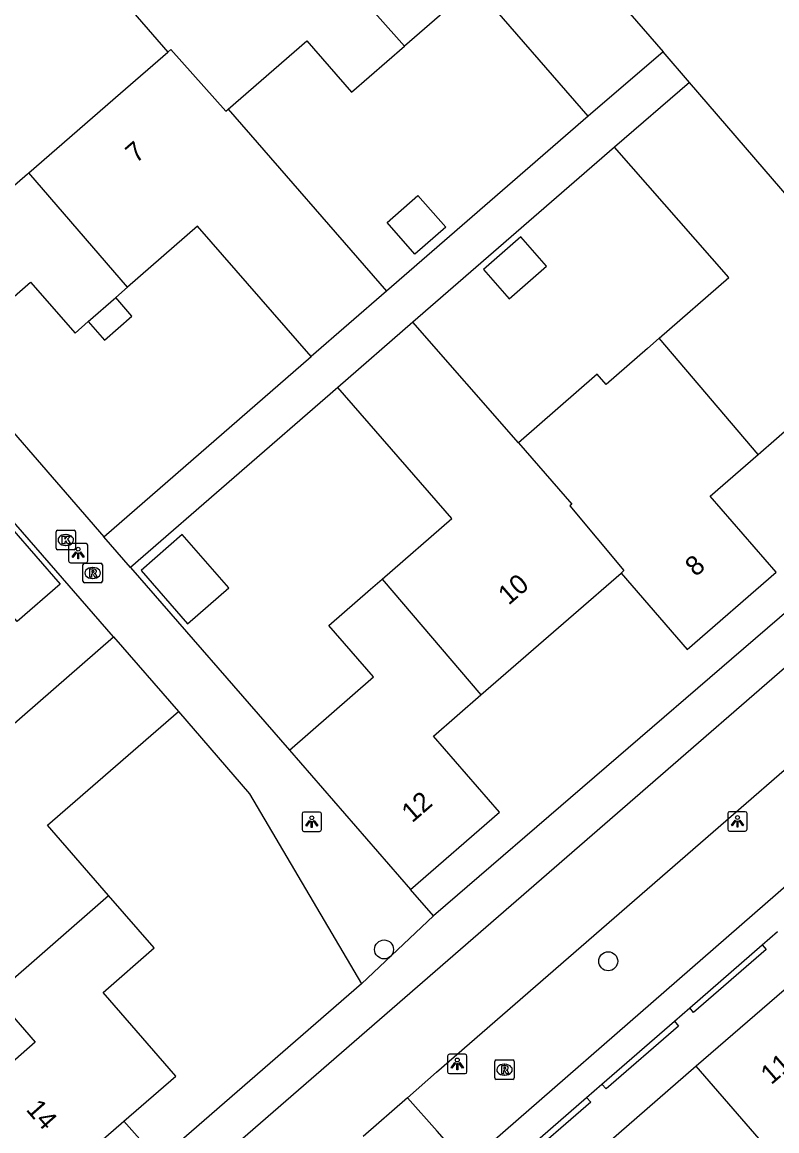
# Model space of a CAD drawing. Extents: x 155888 to 156864, y 383882 to 384671.
# Drawn here: x 156692.5 to 156731.4, y 384304.1 to 384361.3 of the extents above; entities that cross this region are included whole.
import ezdxf

# ---------------------------------------------------------------- set-up
doc = ezdxf.new("R2010")
doc.units = 0
for name, color, linetype in [('IMGEO_Boom', 7, 'Continuous'), ('IMGEO_Kolk', 7, 'Continuous'), ('IMGEO_Lichtpunt', 7, 'Continuous'), ('IMGEO_Muur', 7, 'Continuous'), ('IMGEO_Pand', 7, 'Continuous'), ('IMGEO_Pand_nummerreeks', 7, 'Continuous'), ('IMGEO_Rijbaan_lokaal_gesloten', 7, 'Continuous'), ('IMGEO_Rioolput', 7, 'Continuous'), ('IMGEO_Voetpad_open', 7, 'Continuous')]:
    doc.layers.add(name, color=color, linetype=linetype)

msp = doc.modelspace()

# ---------------------------------------------------------------- linework, layer by layer
at = {"layer": 'IMGEO_Boom'}
for centre in [(156711.122, 384313.445), (156722.688, 384312.836)]:
    msp.add_circle(centre, 0.489, dxfattribs=at)
at = {"layer": 'IMGEO_Kolk'}
for p, q in [((156694.205, 384334.142), (156694.205, 384334.994)), ((156694.28, 384335.068), (156695.132, 384335.068)), ((156694.693, 384334.848), (156694.718, 384334.848)), ((156695.206, 384334.994), (156695.206, 384334.142)), ((156694.716, 384334.288), (156694.691, 384334.288)), ((156695.132, 384334.068), (156694.28, 384334.068))]:
    msp.add_line(p, q, dxfattribs=at)
for points in [[(156694.205, 384334.142), (156694.205, 384334.994)], [(156694.28, 384335.068), (156695.132, 384335.068)], [(156695.206, 384334.994), (156695.206, 384334.142)], [(156694.526, 384334.768), (156694.649, 384334.768), (156694.649, 384334.617), (156694.779, 384334.768), (156694.943, 384334.768), (156694.797, 384334.617), (156694.95, 384334.368), (156694.798, 384334.368), (156694.713, 384334.532), (156694.649, 384334.465), (156694.649, 384334.368), (156694.526, 384334.368), (156694.526, 384334.768)], [(156695.132, 384334.068), (156694.28, 384334.068)]]:
    msp.add_lwpolyline(points, dxfattribs=at)
for centre, start, end in [((156694.282, 384334.992), 91.552, 178.448), ((156694.282, 384334.992), 91.552, 178.448), ((156695.13, 384334.992), 1.552, 88.448), ((156695.13, 384334.992), 1.552, 88.448), ((156694.282, 384334.144), 181.552, 268.448), ((156694.282, 384334.144), 181.552, 268.448), ((156695.13, 384334.144), 271.552, 358.448), ((156695.13, 384334.144), 271.552, 358.448)]:
    msp.add_arc(centre, 0.0765, start, end, dxfattribs=at)
for centre, major_axis, ratio, start_param, end_param in [((156694.692, 384334.568), (-0.387, 0.002), 0.722429, 4.712389, 7.853982), ((156694.717, 384334.568), (-0.39, 0.002), 0.717154, 1.570796, 4.712389)]:
    msp.add_ellipse(centre, major_axis=major_axis, ratio=ratio, start_param=start_param, end_param=end_param, dxfattribs=at)
at = {"layer": 'IMGEO_Lichtpunt'}
for p, q in [((156694.846, 384334.295), (156694.846, 384333.488)), ((156694.846, 384334.295), (156694.846, 384333.488)), ((156695.748, 384334.39), (156694.94, 384334.39)), ((156695.748, 384334.39), (156694.94, 384334.39)), ((156695.842, 384333.488), (156695.842, 384334.295)), ((156695.842, 384333.488), (156695.842, 384334.295)), ((156694.94, 384333.394), (156695.748, 384333.394)), ((156694.94, 384333.394), (156695.748, 384333.394)), ((156707.797, 384320.533), (156706.989, 384320.533)), ((156707.797, 384320.533), (156706.989, 384320.533)), ((156729.756, 384320.551), (156728.948, 384320.551)), ((156729.756, 384320.551), (156728.948, 384320.551)), ((156706.895, 384320.438), (156706.895, 384319.631)), ((156706.895, 384320.438), (156706.895, 384319.631)), ((156707.891, 384319.631), (156707.891, 384320.438)), ((156707.891, 384319.631), (156707.891, 384320.438)), ((156728.854, 384320.456), (156728.854, 384319.649)), ((156728.854, 384320.456), (156728.854, 384319.649)), ((156729.85, 384319.649), (156729.85, 384320.456)), ((156729.85, 384319.649), (156729.85, 384320.456)), ((156706.989, 384319.537), (156707.797, 384319.537)), ((156706.989, 384319.537), (156707.797, 384319.537)), ((156728.948, 384319.555), (156729.756, 384319.555)), ((156728.948, 384319.555), (156729.756, 384319.555)), ((156714.402, 384307.945), (156714.402, 384307.138)), ((156714.402, 384307.945), (156714.402, 384307.138)), ((156715.304, 384308.04), (156714.496, 384308.04)), ((156715.304, 384308.04), (156714.496, 384308.04)), ((156715.398, 384307.138), (156715.398, 384307.945)), ((156715.398, 384307.138), (156715.398, 384307.945)), ((156714.496, 384307.044), (156715.304, 384307.044)), ((156714.496, 384307.044), (156715.304, 384307.044))]:
    msp.add_line(p, q, dxfattribs=at)
for points in [[(156695.22, 384333.959), (156695.259, 384333.931), (156695.071, 384333.669), (156695.033, 384333.696), (156695.22, 384333.959)], [(156695.322, 384333.911), (156695.369, 384333.911), (156695.369, 384333.589), (156695.322, 384333.589), (156695.322, 384333.911)], [(156695.432, 384333.931), (156695.47, 384333.958), (156695.657, 384333.696), (156695.618, 384333.668), (156695.432, 384333.931)], [(156707.269, 384320.102), (156707.308, 384320.074), (156707.12, 384319.812), (156707.082, 384319.839), (156707.269, 384320.102)], [(156707.371, 384320.054), (156707.418, 384320.054), (156707.418, 384319.732), (156707.371, 384319.732), (156707.371, 384320.054)], [(156707.481, 384320.074), (156707.519, 384320.101), (156707.706, 384319.839), (156707.667, 384319.811), (156707.481, 384320.074)], [(156729.228, 384320.12), (156729.267, 384320.092), (156729.079, 384319.83), (156729.041, 384319.857), (156729.228, 384320.12)], [(156729.33, 384320.072), (156729.377, 384320.072), (156729.377, 384319.75), (156729.33, 384319.75), (156729.33, 384320.072)], [(156729.44, 384320.092), (156729.478, 384320.119), (156729.665, 384319.857), (156729.626, 384319.829), (156729.44, 384320.092)], [(156714.776, 384307.609), (156714.815, 384307.581), (156714.627, 384307.319), (156714.589, 384307.346), (156714.776, 384307.609)], [(156714.878, 384307.561), (156714.925, 384307.561), (156714.925, 384307.239), (156714.878, 384307.239), (156714.878, 384307.561)], [(156714.988, 384307.581), (156715.026, 384307.608), (156715.213, 384307.346), (156715.174, 384307.318), (156714.988, 384307.581)]]:
    msp.add_lwpolyline(points, dxfattribs=at)
for centre in [(156695.345, 384334.093), (156707.394, 384320.236), (156729.353, 384320.254), (156714.901, 384307.743)]:
    msp.add_circle(centre, 0.0994, dxfattribs=at)
for centre, start, end in [((156694.94, 384334.295), 90, 180), ((156694.94, 384334.295), 90, 180), ((156695.748, 384334.295), 0, 90), ((156695.748, 384334.295), 0, 90), ((156694.94, 384333.488), 180, 270), ((156694.94, 384333.488), 180, 270), ((156695.748, 384333.488), 270, 0), ((156695.748, 384333.488), 270, 360), ((156706.989, 384320.438), 90, 180), ((156706.989, 384320.438), 90, 180), ((156707.797, 384320.438), 0, 90), ((156707.797, 384320.438), 0, 90), ((156728.948, 384320.456), 90, 180), ((156728.948, 384320.456), 90, 180), ((156729.756, 384320.456), 0, 90), ((156729.756, 384320.456), 0, 90), ((156706.989, 384319.631), 180, 270), ((156706.989, 384319.631), 180, 270), ((156707.797, 384319.631), 270, 0), ((156707.797, 384319.631), 270, 360), ((156728.948, 384319.649), 180, 270), ((156728.948, 384319.649), 180, 270), ((156729.756, 384319.649), 270, 0), ((156729.756, 384319.649), 270, 360), ((156714.496, 384307.945), 90, 180), ((156714.496, 384307.945), 90, 180), ((156715.304, 384307.945), 0, 90), ((156715.304, 384307.945), 0, 90), ((156714.496, 384307.138), 180, 270), ((156714.496, 384307.138), 180, 270), ((156715.304, 384307.138), 270, 0), ((156715.304, 384307.138), 270, 360)]:
    msp.add_arc(centre, 0.0946, start, end, dxfattribs=at)
at = {"layer": 'IMGEO_Muur'}
for points in [[(156700.517, 384325.724), (156704.177, 384321.472), (156709.961, 384311.676)], [(156730.633, 384313.679), (156730.834, 384313.438), (156727.092, 384310.194), (156726.903, 384310.432)], [(156726.903, 384310.432), (156730.633, 384313.679)], [(156709.961, 384311.676), (156699.483, 384302.567)], [(156726.097, 384309.745), (156726.312, 384309.496), (156722.583, 384306.255), (156722.351, 384306.497)], [(156722.351, 384306.497), (156726.097, 384309.745)], [(156721.567, 384305.808), (156721.784, 384305.572), (156718.054, 384302.333), (156717.849, 384302.58)], [(156717.849, 384302.58), (156721.567, 384305.808)], [(156699.483, 384302.567), (156697.695, 384304.581)]]:
    msp.add_lwpolyline(points, dxfattribs=at)
at = {"layer": 'IMGEO_Pand'}
for points in [[(156717.367, 384369.143), (156725.529, 384359.755)], [(156707.021, 384365.86), (156704.559, 384363.722), (156701.172, 384367.647), (156696.585, 384363.656), (156699.974, 384359.741)], [(156712.181, 384360.052), (156707.021, 384365.86)], [(156721.656, 384356.434), (156715.793, 384363.188), (156712.181, 384360.052)], [(156703.086, 384356.802), (156707.147, 384360.327), (156709.446, 384357.678), (156712.181, 384360.052)], [(156692.804, 384353.517), (156697.53, 384357.62), (156699.974, 384359.741)], [(156699.974, 384359.741), (156700.129, 384359.876), (156702.956, 384356.689), (156703.086, 384356.802)], [(156725.529, 384359.755), (156721.656, 384356.434)], [(156726.884, 384358.165), (156723.017, 384354.84)], [(156735.006, 384348.738), (156726.884, 384358.165)], [(156703.086, 384356.802), (156711.25, 384347.399)], [(156692.804, 384353.517), (156692.724, 384353.448), (156690.298, 384351.342), (156686.909, 384355.278), (156682.299, 384351.266)], [(156725.316, 384344.977), (156728.901, 384348.112), (156723.017, 384354.84)], [(156697.895, 384347.611), (156692.804, 384353.517)], [(156712.867, 384352.337), (156714.302, 384350.705), (156712.716, 384349.309), (156711.28, 384350.942), (156712.867, 384352.337)], [(156707.371, 384344.031), (156701.497, 384350.757), (156697.895, 384347.611)], [(156716.254, 384348.525), (156717.573, 384347.017), (156719.498, 384348.7), (156718.179, 384350.209), (156716.254, 384348.525)], [(156688.551, 384344.088), (156692.887, 384347.875), (156695.184, 384345.244), (156695.863, 384345.837)], [(156697.278, 384347.072), (156697.895, 384347.611)], [(156695.863, 384345.837), (156696.694, 384344.885), (156698.109, 384346.121), (156697.278, 384347.072)], [(156695.863, 384345.837), (156697.278, 384347.072)], [(156711.25, 384347.399), (156707.371, 384344.031)], [(156712.61, 384345.805), (156708.731, 384342.437)], [(156718.056, 384339.578), (156712.61, 384345.805)], [(156730.413, 384338.987), (156735.152, 384343.108), (156737.623, 384345.256)], [(156725.316, 384344.977), (156724.714, 384344.45), (156722.586, 384342.589), (156722.115, 384343.128), (156718.056, 384339.578)], [(156730.413, 384338.987), (156725.316, 384344.977)], [(156711.023, 384332.545), (156714.62, 384335.681), (156708.731, 384342.437)], [(156718.056, 384339.578), (156720.815, 384336.423), (156720.7, 384336.323), (156723.499, 384332.991), (156723.35, 384332.862)], [(156723.35, 384332.862), (156726.756, 384328.922), (156731.351, 384332.91), (156727.938, 384336.835), (156730.413, 384338.987)], [(156694.409, 384332.292), (156692.191, 384330.361), (156689.681, 384333.244), (156691.899, 384335.175), (156694.409, 384332.292)], [(156700.991, 384330.25), (156703.113, 384332.1), (156700.713, 384334.852), (156698.591, 384333.001), (156700.991, 384330.25)], [(156706.243, 384323.722), (156710.586, 384327.508), (156708.279, 384330.154), (156710.427, 384332.026), (156711.023, 384332.545)], [(156711.023, 384332.545), (156716.119, 384326.58)], [(156716.119, 384326.58), (156720.89, 384330.725), (156723.35, 384332.862)], [(156687.732, 384321.353), (156697.163, 384329.577)], [(156697.163, 384329.577), (156700.517, 384325.724)], [(156712.495, 384316.534), (156717.079, 384320.53), (156713.671, 384324.453), (156716.119, 384326.58)], [(156696.916, 384316.228), (156693.765, 384319.849), (156700.517, 384325.724)], [(156706.243, 384323.722), (156712.495, 384316.534)], [(156691.016, 384311.093), (156693.131, 384308.665), (156689.211, 384305.218), (156693.203, 384300.685), (156697.695, 384304.581), (156700.384, 384306.913), (156696.628, 384311.229), (156699.268, 384313.525), (156696.916, 384316.228)], [(156691.016, 384311.093), (156696.916, 384316.228)], [(156731.754, 384311.351), (156727.226, 384307.418)], [(156727.226, 384307.418), (156722.699, 384303.485)], [(156734.741, 384298.765), (156727.226, 384307.418)]]:
    msp.add_lwpolyline(points, dxfattribs=at)
at = {"layer": 'IMGEO_Rijbaan_lokaal_gesloten'}
for points in [[(156694.426, 384295.545), (156762.47, 384354.624), (156763.365, 384355.478), (156770.406, 384362.354)], [(156712.324, 384305.79), (156713.826, 384307.107), (156747.484, 384336.347), (156748.988, 384337.664)], [(156712.324, 384305.79), (156710.042, 384303.791)]]:
    msp.add_lwpolyline(points, dxfattribs=at)
at = {"layer": 'IMGEO_Rioolput'}
for p, q in [((156695.591, 384332.44), (156695.591, 384333.292)), ((156695.666, 384333.366), (156696.518, 384333.366)), ((156696.079, 384333.146), (156696.104, 384333.146)), ((156696.592, 384333.292), (156696.592, 384332.44)), ((156696.102, 384332.586), (156696.077, 384332.586)), ((156696.518, 384332.366), (156695.666, 384332.366)), ((156716.836, 384306.817), (156716.836, 384307.669)), ((156716.911, 384307.743), (156717.763, 384307.743)), ((156717.324, 384307.523), (156717.349, 384307.523)), ((156717.837, 384307.669), (156717.837, 384306.817)), ((156717.347, 384306.963), (156717.322, 384306.963)), ((156717.763, 384306.743), (156716.911, 384306.743))]:
    msp.add_line(p, q, dxfattribs=at)
for points in [[(156695.591, 384332.44), (156695.591, 384333.292)], [(156695.666, 384333.366), (156696.518, 384333.366)], [(156696.592, 384333.292), (156696.592, 384332.44)], [(156696.18, 384333.064), (156695.928, 384333.066), (156695.928, 384332.666)], [(156695.928, 384332.666), (156696.052, 384332.666), (156696.052, 384332.828), (156696.063, 384332.828)], [(156696.106, 384332.985), (156696.052, 384332.985), (156696.052, 384332.904)], [(156696.052, 384332.904), (156696.104, 384332.904)], [(156696.11, 384332.799), (156696.181, 384332.666), (156696.321, 384332.666), (156696.256, 384332.792)], [(156696.518, 384332.366), (156695.666, 384332.366)], [(156716.836, 384306.817), (156716.836, 384307.669)], [(156716.911, 384307.743), (156717.763, 384307.743)], [(156717.425, 384307.441), (156717.173, 384307.443), (156717.173, 384307.043)], [(156717.837, 384307.669), (156717.837, 384306.817)], [(156717.173, 384307.043), (156717.297, 384307.043), (156717.297, 384307.205), (156717.308, 384307.205)], [(156717.351, 384307.362), (156717.297, 384307.362), (156717.297, 384307.281)], [(156717.297, 384307.281), (156717.349, 384307.281)], [(156717.355, 384307.176), (156717.426, 384307.043), (156717.566, 384307.043), (156717.501, 384307.169)], [(156717.763, 384306.743), (156716.911, 384306.743)]]:
    msp.add_lwpolyline(points, dxfattribs=at)
for centre, radius, start, end in [((156695.668, 384333.29), 0.0765, 91.552, 178.448), ((156695.668, 384333.29), 0.0765, 91.552, 178.448), ((156696.516, 384333.29), 0.0765, 1.552, 88.448), ((156696.516, 384333.29), 0.0765, 1.552, 88.448), ((156696.062, 384332.775), 0.0533, 26.0293, 88.6989), ((156696.088, 384333.093), 0.19, 274.7715, 282.9687), ((156696.112, 384332.889), 0.0964, 77.0061, 93.1865), ((156696.126, 384332.946), 0.0378, 276.6634, 79.6772), ((156696.179, 384332.954), 0.109, 350.3612, 89.416), ((156696.177, 384332.954), 0.112, 277.5842, 350.9817), ((156696.161, 384332.739), 0.108, 29.5134, 73.7905), ((156695.668, 384332.442), 0.0765, 181.552, 268.448), ((156695.668, 384332.442), 0.0765, 181.552, 268.448), ((156696.516, 384332.442), 0.0765, 271.552, 358.448), ((156696.516, 384332.442), 0.0765, 271.552, 358.448), ((156716.913, 384307.667), 0.0765, 91.552, 178.448), ((156716.913, 384307.667), 0.0765, 91.552, 178.448), ((156717.424, 384307.331), 0.109, 350.3612, 89.416), ((156717.761, 384307.667), 0.0765, 1.552, 88.448), ((156717.761, 384307.667), 0.0765, 1.552, 88.448), ((156716.913, 384306.819), 0.0765, 181.552, 268.448), ((156716.913, 384306.819), 0.0765, 181.552, 268.448), ((156717.307, 384307.152), 0.0533, 26.0293, 88.6989), ((156717.333, 384307.47), 0.19, 274.7715, 282.9687), ((156717.357, 384307.266), 0.0964, 77.0061, 93.1865), ((156717.371, 384307.323), 0.0378, 276.6634, 79.6772), ((156717.422, 384307.331), 0.112, 277.5842, 350.9817), ((156717.406, 384307.116), 0.108, 29.5134, 73.7905), ((156717.761, 384306.819), 0.0765, 271.552, 358.448), ((156717.761, 384306.819), 0.0765, 271.552, 358.448)]:
    msp.add_arc(centre, radius, start, end, dxfattribs=at)
for centre, major_axis, ratio, start_param, end_param in [((156696.078, 384332.866), (-0.387, 0.002), 0.722429, 4.712389, 7.853982), ((156696.103, 384332.866), (-0.39, 0.002), 0.717154, 1.570796, 4.712389), ((156717.323, 384307.243), (-0.387, 0.002), 0.722429, 4.712389, 7.853982), ((156717.348, 384307.243), (-0.39, 0.002), 0.717154, 1.570796, 4.712389)]:
    msp.add_ellipse(centre, major_axis=major_axis, ratio=ratio, start_param=start_param, end_param=end_param, dxfattribs=at)
at = {"layer": 'IMGEO_Voetpad_open'}
for points in [[(156726.884, 384358.165), (156725.529, 384359.755)], [(156721.656, 384356.434), (156711.25, 384347.399)], [(156723.017, 384354.84), (156712.61, 384345.805)], [(156749.568, 384346.138), (156746.899, 384343.79), (156713.668, 384315.177)], [(156688.551, 384344.088), (156696.673, 384334.738)], [(156696.673, 384334.738), (156707.371, 384344.031)], [(156708.731, 384342.437), (156698.047, 384333.156)], [(156697.163, 384329.577), (156688.097, 384339.98)], [(156748.988, 384337.664), (156750.444, 384335.978), (156751.947, 384334.237), (156715.384, 384302.356), (156713.856, 384304.071), (156712.324, 384305.79)], [(156698.047, 384333.156), (156696.673, 384334.738)], [(156698.047, 384333.156), (156706.243, 384323.722)], [(156700.517, 384325.724), (156704.177, 384321.472), (156709.961, 384311.676)], [(156713.668, 384315.177), (156712.495, 384316.534)], [(156709.961, 384311.676), (156713.668, 384315.177)], [(156730.633, 384313.679), (156731.416, 384314.376)], [(156709.961, 384311.676), (156699.483, 384302.567), (156693.423, 384297.378)], [(156726.097, 384309.745), (156726.903, 384310.432)], [(156721.567, 384305.808), (156722.351, 384306.497)]]:
    msp.add_lwpolyline(points, dxfattribs=at)

# ---------------------------------------------------------------- texts
at = {"layer": 'IMGEO_Pand_nummerreeks'}
for s, rotation, p in [('7', 40.9588, (156698.332, 384353.972)), ('8', 40.955, (156727.198, 384332.641)), ('10', 40.8748, (156717.547, 384331.172)), ('12', 41.0811, (156712.573, 384319.947)), ('11', 40.9805, (156731.094, 384306.433)), ('14', 311.3689, (156692.612, 384305.168))]:
    msp.add_text(s, height=1, rotation=rotation, dxfattribs=at).set_placement(p)

doc.saveas('drawing.dxf')
